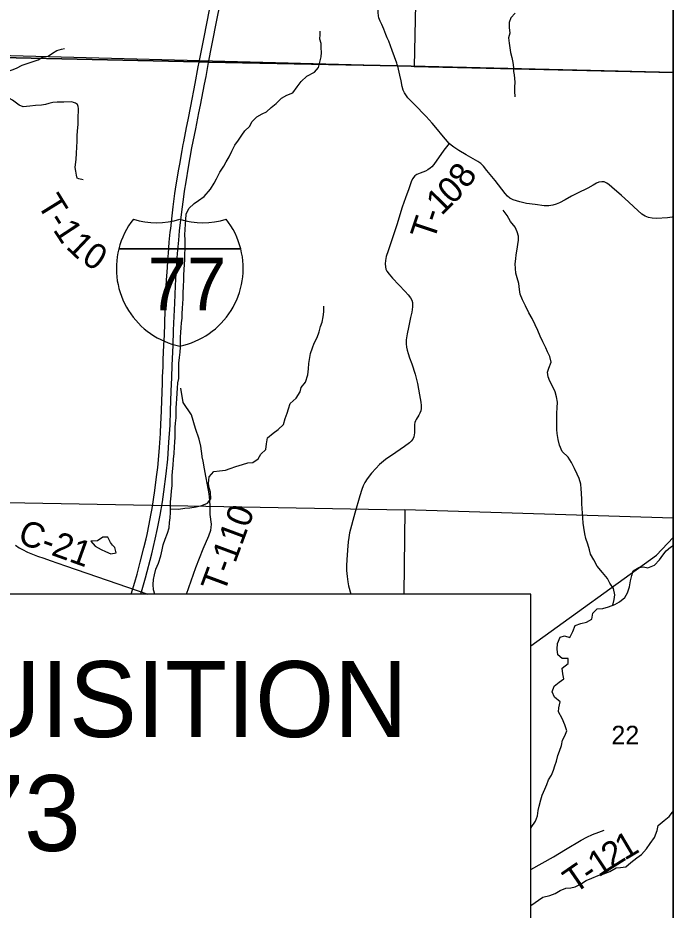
# Model space of a CAD drawing. Extents: x 0 to 34, y 0 to 22.
# Drawn here: x 6.964 to 8.431, y 18.153 to 20.15 of the extents above; entities that cross this region are included whole.
import ezdxf

# ---------------------------------------------------------------- set-up
doc = ezdxf.new("R2010")
doc.units = 0
for name, color, linetype in [('GM_X_Corporation', 7, 'Continuous'), ('GM_X_County_Road', 7, 'Continuous'), ('GM_X_County_Road_Text', 7, 'Continuous'), ('GM_X_Interstate_Location', 7, 'Continuous'), ('GM_X_Interstate_Route', 7, 'Continuous'), ('GM_X_Interstate_Shield', 7, 'Continuous'), ('GM_X_Minor_Lake', 7, 'Continuous'), ('GM_X_Minor_River', 7, 'Continuous'), ('GM_X_Section_Text', 7, 'Continuous'), ('GM_X_Township_Road', 7, 'Continuous'), ('GM_X_Township_Road_Text', 7, 'Continuous'), ('SH_Data', 7, 'Continuous'), ('SH_Text', 7, 'Continuous')]:
    doc.layers.add(name, color=color, linetype=linetype)

msp = doc.modelspace()

# ---------------------------------------------------------------- linework, layer by layer
at = {"layer": 'GM_X_Corporation'}
for points in [[(4.7823, 18.128), (4.7905, 18.3604), (4.8074, 19.5455), (4.8169, 20.042), (4.8194, 20.1261), (5.11, 20.116), (6.0551, 20.0845), (6.4901, 20.0752), (6.7204, 20.0659), (7.3691, 20.0515), (7.3901, 20.051), (7.814, 20.0425), (8.4311, 20.028), (8.4311, 21.3734), (1.6311, 21.3734)], [(4.0508, 18.1454), (4.7823, 18.128), (4.7905, 18.3604), (4.8074, 19.5455), (4.8169, 20.042), (4.8194, 20.1261), (5.11, 20.116), (6.0551, 20.0845), (6.4901, 20.0752), (6.7204, 20.0659), (7.3691, 20.0515), (7.3901, 20.051), (7.814, 20.0425), (8.4311, 20.028), (8.4311, 21.3734), (2.7987, 21.3734)], [(8.4311, 14.5734), (8.4311, 20.028), (7.814, 20.0425), (7.3901, 20.051), (7.3691, 20.0515), (6.7204, 20.0659), (6.4901, 20.0752), (6.0551, 20.0845), (5.11, 20.116), (4.8194, 20.1261), (4.8169, 20.042), (4.8074, 19.5455), (4.7905, 18.3604), (4.7823, 18.128)], [(8.4311, 16.0029), (8.4311, 20.028), (7.814, 20.0425), (7.3901, 20.051), (7.3691, 20.0515), (6.7204, 20.0659), (6.4901, 20.0752), (6.0551, 20.0845), (5.11, 20.116), (4.8194, 20.1261), (4.8169, 20.042), (4.8074, 19.5455), (4.7905, 18.3604), (4.7823, 18.128)], [(6.8097, 18.8602), (6.8161, 19.0676), (7.8304, 19.049), (7.8278, 18.8602)], [(7.8172, 18.0831), (7.817, 18.0695), (8.4311, 18.0575), (8.4311, 19.0302), (7.8304, 19.049), (7.8278, 18.8602)]]:
    msp.add_lwpolyline(points, dxfattribs=at)
for points in [[(7.8729, 21.0548), (7.8512, 20.0413), (6.8338, 20.0683), (6.8544, 21.0806)], [(8.4311, 20.0277), (8.4311, 21.0375), (7.8729, 21.0548), (7.8512, 20.0413)]]:
    msp.add_lwpolyline(points, close=True, dxfattribs=at)
at = {"layer": 'GM_X_County_Road'}
for points in [[(7.8142, 20.0419), (7.813, 20.0458), (7.812, 20.0487), (7.8069, 20.0627), (7.8021, 20.0771), (7.794, 20.0979), (7.791, 20.1052), (7.788, 20.1128), (7.7828, 20.1248), (7.7787, 20.1349), (7.7753, 20.143), (7.7722, 20.1503), (7.7711, 20.1543), (7.7706, 20.1623), (7.7703, 20.1705), (7.7703, 20.1795), (7.7703, 20.1879), (7.7706, 20.202), (7.7705, 20.2179), (7.7708, 20.2248), (7.7715, 20.2378), (7.7723, 20.2489), (7.7729, 20.2552)], [(8.4311, 19.7043), (8.429, 19.7038), (8.4182, 19.7022), (8.3939, 19.7011), (8.3844, 19.7018), (8.3758, 19.703), (8.3682, 19.7063), (8.3607, 19.7108), (8.3432, 19.7272), (8.3314, 19.738), (8.3151, 19.7521), (8.2938, 19.771), (8.2875, 19.7766), (8.2827, 19.7803), (8.2765, 19.7827), (8.2711, 19.7833), (8.2644, 19.7823), (8.2593, 19.7801), (8.2522, 19.7753), (8.2403, 19.7685), (8.2172, 19.7573), (8.2034, 19.7506), (8.1896, 19.743), (8.1769, 19.7363), (8.1688, 19.7331), (8.1616, 19.7308), (8.1527, 19.7293), (8.142, 19.7294), (8.1218, 19.7321), (8.1029, 19.7348), (8.0874, 19.7379), (8.0728, 19.7426), (8.0653, 19.7466), (8.0601, 19.7511), (8.0546, 19.7572), (8.0322, 19.7861), (8.0138, 19.8086), (8.0063, 19.818), (8.0001, 19.8242), (7.9936, 19.8285), (7.9674, 19.8434), (7.9515, 19.8529), (7.9398, 19.8606), (7.9338, 19.8653), (7.9292, 19.8691), (7.9214, 19.8787), (7.9129, 19.8884), (7.9035, 19.9001), (7.8915, 19.914), (7.878, 19.9295), (7.8509, 19.9571), (7.8429, 19.9648), (7.8371, 19.9711), (7.8336, 19.9752), (7.8291, 19.9821), (7.8264, 19.9881), (7.8239, 19.9965), (7.8218, 20.0089), (7.8193, 20.0215), (7.8142, 20.0419)], [(6.9585, 18.9695), (6.9663, 18.9641), (6.9739, 18.9598), (6.9855, 18.9538), (7.0078, 18.9452), (7.022, 18.9403), (7.0359, 18.9356), (7.0703, 18.9238), (7.1178, 18.9074), (7.2549, 18.8602)]]:
    msp.add_lwpolyline(points, dxfattribs=at)
at = {"layer": 'GM_X_Interstate_Route'}
for points in [[(7.3904, 20.0505), (7.3978, 20.088), (7.4101, 20.1489), (7.421, 20.2038)], [(7.3693, 20.0509), (7.3805, 20.1066), (7.3927, 20.1682)], [(7.2174, 18.8602), (7.2204, 18.8698), (7.2254, 18.8869), (7.2306, 18.9048), (7.2378, 18.9314), (7.2458, 18.9635), (7.2506, 18.9841), (7.2528, 18.9937), (7.2575, 19.0166), (7.2613, 19.0368), (7.2641, 19.052), (7.2704, 19.0924), (7.2741, 19.1225), (7.2767, 19.1437), (7.2775, 19.1519), (7.2808, 19.1882), (7.2829, 19.2195), (7.2838, 19.243), (7.2842, 19.2528), (7.2857, 19.2923), (7.2872, 19.3326), (7.2878, 19.3468), (7.2888, 19.3689), (7.2892, 19.3857), (7.2906, 19.4172), (7.2916, 19.4401), (7.2926, 19.4658), (7.2937, 19.4963), (7.2947, 19.5175), (7.2952, 19.534), (7.2967, 19.5638), (7.2976, 19.5807), (7.2991, 19.6041), (7.2996, 19.6103), (7.3006, 19.6223), (7.3027, 19.6478), (7.305, 19.6702), (7.3058, 19.6786), (7.3091, 19.7066), (7.3116, 19.7269), (7.3154, 19.7566), (7.3183, 19.776), (7.324, 19.8111), (7.326, 19.8225), (7.3315, 19.8535), (7.3341, 19.8666), (7.3352, 19.8723), (7.3415, 19.9043), (7.3449, 19.9221), (7.351, 19.9526), (7.361, 20.0033), (7.3674, 20.0401), (7.3693, 20.0509)], [(7.2386, 18.8602), (7.2497, 18.8969), (7.2639, 18.9507), (7.2713, 18.983), (7.2763, 19.0067), (7.282, 19.037), (7.2872, 19.0666), (7.2906, 19.0894), (7.2956, 19.1297), (7.2992, 19.162), (7.302, 19.2006), (7.3043, 19.2385), (7.3054, 19.2715), (7.3062, 19.2929), (7.3069, 19.3146), (7.3082, 19.3448), (7.3092, 19.3726), (7.311, 19.4164), (7.3124, 19.4503), (7.3131, 19.4668), (7.3148, 19.5117), (7.3165, 19.55), (7.3172, 19.565), (7.3195, 19.6015), (7.3211, 19.6223), (7.3237, 19.6527), (7.3259, 19.6732), (7.3313, 19.722), (7.3342, 19.7433), (7.3371, 19.7618), (7.3402, 19.7828), (7.3455, 19.8158), (7.3533, 19.8591), (7.3562, 19.8732), (7.362, 19.9018), (7.3689, 19.9375), (7.3723, 19.9544), (7.3815, 20.0013), (7.3851, 20.019), (7.3904, 20.0505)]]:
    msp.add_lwpolyline(points, dxfattribs=at)
at = {"layer": 'GM_X_Interstate_Shield'}
for p, q in [((7.1895, 19.6328), (7.4628, 19.6328)), ((7.4628, 19.6328), (7.1895, 19.6328)), ((7.4628, 19.6328), (7.1895, 19.6328))]:
    msp.add_line(p, q, dxfattribs=at)
for centre, start, end in [((7.3617, 19.5893), 141.669, 165.8066), ((7.2743, 19.8692), 253.0091, 286.9909), ((7.378, 19.8692), 253.0091, 286.9909), ((7.2906, 19.5893), 14.1934, 38.331), ((7.3617, 19.5893), 165.8066, 258.463), ((7.2906, 19.5893), 281.537, 14.1934)]:
    msp.add_arc(centre, 0.1776, start, end, dxfattribs=at)
at = {"layer": 'GM_X_Minor_Lake'}
for points in [[(7.1758, 18.9701), (7.1711, 18.9756), (7.1654, 18.9877), (7.1541, 18.9874), (7.1416, 18.9794), (7.1269, 18.9787)], [(7.1269, 18.9787), (7.1367, 18.9673), (7.1499, 18.9601), (7.1601, 18.9552), (7.1718, 18.9502), (7.1839, 18.9525), (7.1809, 18.9642), (7.1758, 18.9701)]]:
    msp.add_lwpolyline(points, dxfattribs=at)
at = {"layer": 'GM_X_Minor_River'}
for points in [[(8.0772, 20.1607), (8.0679, 20.15), (8.0638, 20.1397), (8.0635, 20.1287), (8.0655, 20.1159), (8.0626, 20.1052), (8.0638, 20.0931), (8.0654, 20.0833), (8.067, 20.0723), (8.0698, 20.061), (8.0721, 20.05), (8.0737, 20.039), (8.0738, 20.0296), (8.0742, 20.0281)], [(7.6371, 20.0393), (7.64, 20.0512), (7.643, 20.0626), (7.6432, 20.0728), (7.6428, 20.083), (7.6427, 20.0929), (7.6396, 20.1027), (7.6406, 20.1126), (7.6409, 20.1205)], [(7.009, 20.0558), (7.0196, 20.0629), (7.0313, 20.0641), (7.0411, 20.0707), (7.0512, 20.0768), (7.061, 20.0803), (7.0682, 20.0812)], [(6.7478, 20.0636), (6.7572, 20.0549), (6.7689, 20.0466), (6.7806, 20.0401), (6.7935, 20.0344), (6.8074, 20.0314), (6.8176, 20.0287), (6.8305, 20.0245), (6.843, 20.0196), (6.8528, 20.0165), (6.8668, 20.0138), (6.877, 20.0142), (6.8902, 20.0153), (6.9023, 20.0157), (6.9148, 20.0191), (6.9284, 20.0255), (6.9402, 20.0297), (6.9508, 20.0334), (6.9606, 20.0376), (6.9731, 20.044), (6.9891, 20.0495), (7.009, 20.0558)], [(7.3352, 19.5636), (7.3352, 19.5731), (7.336, 19.5875), (7.3368, 19.5974), (7.3376, 19.6095), (7.3372, 19.6205), (7.338, 19.6338), (7.3384, 19.6436), (7.3384, 19.6535), (7.3377, 19.6641), (7.3381, 19.6766), (7.3392, 19.688), (7.34, 19.6978), (7.3408, 19.7107), (7.3465, 19.7232), (7.3586, 19.7346), (7.3684, 19.741), (7.3809, 19.7501), (7.395, 19.7663), (7.4029, 19.78), (7.4086, 19.7895), (7.4158, 19.8046), (7.4246, 19.8179), (7.4302, 19.8277), (7.4367, 19.8391), (7.4428, 19.8519), (7.4492, 19.8648), (7.4579, 19.8762), (7.4651, 19.8875), (7.4716, 19.8974), (7.4822, 19.9068), (7.4883, 19.9178), (7.4985, 19.9284), (7.5106, 19.9349), (7.5205, 19.9398), (7.5307, 19.9492), (7.5417, 19.9587), (7.5538, 19.9704), (7.5663, 19.9772), (7.5792, 19.9825), (7.589, 19.9954), (7.5977, 20.0079), (7.6106, 20.0196), (7.628, 20.0284), (7.6371, 20.0393)], [(8.0742, 20.0281), (8.0757, 20.0152), (8.0768, 20.0053), (8.0761, 19.9958), (8.0761, 19.9856), (8.0764, 19.9735)], [(8.296, 18.8354), (8.2989, 18.8478), (8.3004, 18.8584), (8.2978, 18.8725), (8.2895, 18.885), (8.2838, 18.8948), (8.2729, 18.9085), (8.2612, 18.9225), (8.2537, 18.9366), (8.2461, 18.9495), (8.2435, 18.959), (8.2397, 18.9718), (8.2356, 18.9847), (8.233, 18.995), (8.2311, 19.0094), (8.2296, 19.0189), (8.2289, 19.031), (8.2278, 19.0412), (8.2274, 19.0515), (8.2267, 19.0621), (8.2263, 19.0719), (8.226, 19.0863), (8.2252, 19.0958), (8.2245, 19.106), (8.2207, 19.1186), (8.2162, 19.1288), (8.2098, 19.1417), (8.2038, 19.1546), (8.1959, 19.1667), (8.1827, 19.1793), (8.1763, 19.1937), (8.1736, 19.2066), (8.1714, 19.2194), (8.1707, 19.2289), (8.1707, 19.2653), (8.1711, 19.2774), (8.1723, 19.2896), (8.1697, 19.3017), (8.1667, 19.3131), (8.1618, 19.3241), (8.1546, 19.3366), (8.1512, 19.3465), (8.1497, 19.3567), (8.1528, 19.3662), (8.1577, 19.379), (8.1547, 19.3919), (8.1498, 19.4022), (8.1457, 19.4117), (8.1396, 19.4246), (8.1336, 19.4378), (8.1283, 19.4503), (8.1223, 19.4629), (8.1155, 19.4773), (8.108, 19.4898), (8.1005, 19.5057), (8.0937, 19.5186), (8.0888, 19.5315), (8.0873, 19.5417), (8.0854, 19.5554), (8.0821, 19.5683), (8.0791, 19.5785), (8.0779, 19.5891), (8.0776, 19.5998), (8.0787, 19.6104), (8.0799, 19.6198), (8.0814, 19.632), (8.0833, 19.6426), (8.0845, 19.6521), (8.0845, 19.6615), (8.0819, 19.671), (8.0774, 19.6812), (8.0672, 19.6945), (8.0593, 19.7074), (8.0506, 19.7199)], [(7.2705, 18.8601), (7.2673, 18.8697), (7.2666, 18.8815), (7.267, 18.8932), (7.2696, 18.9035), (7.2723, 18.916), (7.2788, 18.9296), (7.2841, 18.9459), (7.2871, 18.9592), (7.2891, 18.9705), (7.2936, 18.9834), (7.2986, 18.9967), (7.3024, 19.0088), (7.3035, 19.0205), (7.3047, 19.0311), (7.3051, 19.0425), (7.3051, 19.0543), (7.3055, 19.0668), (7.3067, 19.08), (7.3078, 19.091), (7.3094, 19.1024), (7.3094, 19.1123), (7.309, 19.1251), (7.3098, 19.135), (7.3113, 19.149), (7.3121, 19.1619), (7.3133, 19.1748), (7.3144, 19.1899), (7.3152, 19.2006), (7.3156, 19.2112), (7.3157, 19.2328), (7.3164, 19.2426), (7.318, 19.2551), (7.318, 19.2646), (7.3184, 19.2775), (7.3192, 19.287), (7.3196, 19.2976), (7.3203, 19.3097), (7.3211, 19.3215), (7.3219, 19.3328), (7.3238, 19.3427), (7.3242, 19.3522), (7.3243, 19.3772), (7.3254, 19.3897), (7.3269, 19.4014), (7.3281, 19.4128), (7.3281, 19.4352), (7.3285, 19.4454), (7.3293, 19.4568), (7.3301, 19.4674), (7.3313, 19.4776), (7.3317, 19.4878), (7.3321, 19.5004), (7.3332, 19.511), (7.3336, 19.5208), (7.3336, 19.5345), (7.3344, 19.5489), (7.3352, 19.5636)], [(7.3051, 19.0509), (7.3236, 19.0504), (7.3376, 19.0527), (7.3486, 19.0531), (7.363, 19.0557), (7.3758, 19.0587), (7.3883, 19.0636), (7.3959, 19.0735), (7.3948, 19.0883), (7.3922, 19.0981), (7.3903, 19.1076), (7.3918, 19.1224), (7.4021, 19.1345), (7.4149, 19.136), (7.4285, 19.1375), (7.4388, 19.1413), (7.452, 19.1458), (7.4664, 19.1503), (7.4789, 19.1537), (7.4895, 19.1548), (7.5016, 19.1632), (7.5076, 19.1734), (7.5186, 19.184), (7.5202, 19.1965), (7.5228, 19.2097), (7.535, 19.2203), (7.5467, 19.2283), (7.5588, 19.24), (7.5623, 19.2529), (7.5668, 19.265), (7.5695, 19.2749), (7.5737, 19.2866), (7.5865, 19.2991), (7.5956, 19.3131), (7.5983, 19.3226), (7.6074, 19.3347), (7.6127, 19.351), (7.6143, 19.3643), (7.6154, 19.3764), (7.6193, 19.3984), (7.6234, 19.4116), (7.6269, 19.4219), (7.6337, 19.4347), (7.6386, 19.4469), (7.6413, 19.459), (7.6447, 19.4692), (7.6474, 19.4806), (7.6489, 19.4919), (7.6486, 19.5048)], [(8.174, 18.5966), (8.1751, 18.6058), (8.1782, 18.6187), (8.1657, 18.6293), (8.1605, 18.6418), (8.1643, 18.6543), (8.176, 18.6634), (8.1862, 18.6706), (8.184, 18.682), (8.1829, 18.6945), (8.1957, 18.7047), (8.1961, 18.7164), (8.1829, 18.7161), (8.1731, 18.7244), (8.1712, 18.7366), (8.172, 18.7498), (8.1777, 18.7638), (8.1879, 18.7665), (8.2, 18.7631), (8.2065, 18.7763), (8.2114, 18.7899), (8.2247, 18.7945), (8.2368, 18.7975), (8.2489, 18.8039), (8.2512, 18.8179), (8.2606, 18.8274), (8.2735, 18.8281), (8.2864, 18.8315), (8.3004, 18.8372), (8.311, 18.8429), (8.3227, 18.8527), (8.3292, 18.8633), (8.3337, 18.8762), (8.3356, 18.8898), (8.3383, 18.9016), (8.3413, 18.9122), (8.3542, 18.9198), (8.3644, 18.9216), (8.3743, 18.9193), (8.3894, 18.925), (8.4004, 18.9367), (8.4083, 18.9474), (8.4152, 18.9572), (8.4254, 18.9651), (8.4311, 18.9687)], [(8.1124, 18.3357), (8.1132, 18.3374), (8.1227, 18.3519), (8.1272, 18.364), (8.129, 18.3758), (8.1313, 18.3856), (8.135, 18.3997), (8.138, 18.4099), (8.144, 18.4232), (8.1485, 18.4338), (8.1523, 18.4441), (8.1583, 18.4547), (8.1632, 18.4661), (8.1658, 18.4756), (8.1696, 18.4862), (8.173, 18.4987), (8.1763, 18.509), (8.1809, 18.5215), (8.1835, 18.5336), (8.1884, 18.5431), (8.1932, 18.5545), (8.1887, 18.5674), (8.1826, 18.5814), (8.174, 18.5966)], [(8.1124, 18.163), (8.1394, 18.1817), (8.155, 18.1859), (8.1671, 18.1898), (8.1784, 18.1966), (8.1905, 18.2016), (8.2019, 18.2024), (8.2117, 18.2047), (8.2238, 18.2112), (8.2366, 18.2192), (8.2487, 18.2242), (8.2631, 18.2303), (8.2756, 18.2341), (8.2892, 18.2395), (8.3036, 18.2475), (8.3134, 18.2479), (8.3252, 18.2498), (8.3361, 18.2597), (8.3497, 18.27), (8.3599, 18.2776), (8.3716, 18.2902), (8.3799, 18.3019), (8.3893, 18.3156), (8.395, 18.3312), (8.3976, 18.3422), (8.4112, 18.3532), (8.4225, 18.3624), (8.4297, 18.3719), (8.4311, 18.3748)]]:
    msp.add_lwpolyline(points, dxfattribs=at)
at = {"layer": 'GM_X_Township_Road'}
for points in [[(7.036, 19.9594), (7.0331, 19.9587), (7.0254, 19.9562), (7.0168, 19.9548), (7.0029, 19.9538), (6.9904, 19.9522), (6.9828, 19.9513), (6.9755, 19.9508), (6.9666, 19.955), (6.9513, 19.966), (6.9278, 19.9793), (6.8904, 20.0021), (6.8838, 20.0048), (6.878, 20.0065), (6.8688, 20.0088), (6.8519, 20.0137), (6.833, 20.0196), (6.7844, 20.0364), (6.751, 20.0483), (6.7337, 20.0533), (6.7297, 20.0554), (6.7259, 20.0587), (6.7206, 20.0654)], [(7.11, 19.7874), (7.0999, 19.7899), (7.0966, 19.7915), (7.0948, 19.7979), (7.0933, 19.8069), (7.0918, 19.8154), (7.0936, 19.8276), (7.0945, 19.8331), (7.0949, 19.8474), (7.0967, 19.8739), (7.0967, 19.886), (7.0973, 19.8973), (7.0988, 19.9116), (7.0988, 19.9187), (7.0986, 19.9273), (7.0993, 19.9436), (7.0993, 19.9474), (7.0984, 19.9513), (7.0971, 19.9558), (7.0924, 19.9591), (7.0884, 19.9609), (7.0846, 19.9619), (7.0663, 19.9617), (7.0513, 19.9615), (7.0419, 19.9607), (7.036, 19.9594)], [(7.9292, 19.8691), (7.9178, 19.8537), (7.8955, 19.8218), (7.8905, 19.8164), (7.8869, 19.8135), (7.8818, 19.8099), (7.8766, 19.8072), (7.8648, 19.8027), (7.8572, 19.7992), (7.8524, 19.7962), (7.8476, 19.7901), (7.8441, 19.7827), (7.839, 19.7676), (7.8317, 19.7474), (7.8244, 19.7265), (7.8192, 19.7089), (7.8128, 19.6887), (7.803, 19.6601), (7.7972, 19.6423), (7.7929, 19.6288), (7.7886, 19.6159), (7.7868, 19.6071), (7.7863, 19.5998), (7.7869, 19.5929), (7.788, 19.5877), (7.7901, 19.5831), (7.7952, 19.576), (7.8023, 19.5676), (7.8313, 19.5376), (7.8377, 19.5301), (7.8428, 19.5232), (7.8455, 19.5182), (7.8472, 19.5128), (7.8477, 19.503), (7.8456, 19.4916), (7.8427, 19.4791), (7.8384, 19.4567), (7.8354, 19.4428), (7.8334, 19.4292), (7.833, 19.4204), (7.8336, 19.4131), (7.8351, 19.406), (7.8375, 19.3989), (7.8409, 19.3887), (7.8459, 19.3755), (7.8532, 19.3527), (7.8584, 19.3315), (7.8631, 19.306), (7.8664, 19.2895), (7.8669, 19.2827), (7.867, 19.2755), (7.866, 19.2706), (7.8638, 19.2654), (7.8612, 19.2605), (7.8558, 19.2511), (7.8541, 19.2478), (7.8526, 19.2445), (7.8518, 19.2396), (7.8517, 19.2344), (7.8516, 19.2212), (7.8501, 19.2126), (7.8478, 19.2072), (7.8446, 19.2028), (7.8406, 19.1991), (7.8296, 19.1908), (7.8104, 19.1773), (7.7866, 19.1614), (7.7737, 19.1502), (7.765, 19.1416), (7.7558, 19.1309), (7.746, 19.1184), (7.7407, 19.1102), (7.737, 19.1029), (7.7336, 19.0942), (7.7296, 19.0805), (7.7184, 19.0414), (7.7064, 18.9975), (7.7046, 18.9868), (7.7033, 18.9772), (7.7016, 18.9587), (7.7, 18.9368), (7.6995, 18.9242), (7.6996, 18.9127), (7.7012, 18.8995), (7.7027, 18.8877), (7.7044, 18.879), (7.7091, 18.8602)], [(7.3762, 19.1688), (7.3732, 19.1914), (7.3693, 19.2071), (7.3616, 19.2307), (7.3521, 19.2615), (7.3335, 19.289), (7.3289, 19.3209)], [(7.3409, 18.8602), (7.3623, 18.9195), (7.3702, 18.9404), (7.3785, 18.9613), (7.3911, 18.991), (7.3954, 19.003), (7.3967, 19.0095), (7.3969, 19.0166), (7.3946, 19.0382), (7.3944, 19.057), (7.3936, 19.0699), (7.3918, 19.0847), (7.3884, 19.1045), (7.3842, 19.1243), (7.3814, 19.1403), (7.3784, 19.158), (7.3764, 19.1677), (7.3762, 19.1688)], [(8.1124, 18.7446), (8.3935, 18.9477), (8.4311, 18.9872)], [(8.1124, 18.244), (8.1628, 18.2724), (8.1898, 18.2887), (8.2252, 18.3094), (8.238, 18.3161), (8.2504, 18.322), (8.2644, 18.3276), (8.2763, 18.3315)]]:
    msp.add_lwpolyline(points, dxfattribs=at)
at = {"layer": 'SH_Data'}
msp.add_lwpolyline([(5.6652, 18.0831), (8.1124, 18.0831), (8.1124, 18.8602), (5.6652, 18.8602)], close=True, dxfattribs=at)
at = {"layer": 'SH_Text'}
msp.add_line((8.4311, 21.373), (8.4311, 14.5734), dxfattribs=at)

# ---------------------------------------------------------------- texts
at = {"layer": 'GM_X_County_Road_Text'}
msp.add_text('C-21', height=0.05682, rotation=340.163, dxfattribs=at).set_placement((6.9606, 18.9757))
at = {"layer": 'GM_X_Interstate_Location'}
for s in ['-', '.', ',']:
    msp.add_text(s, height=0.000189, dxfattribs=at).set_placement((7.3261, 19.5573))
msp.add_text('77', height=0.000189, rotation=0, dxfattribs=at).set_placement((7.2874, 19.5181))
at = {"layer": 'GM_X_Interstate_Shield'}
msp.add_text('77', height=0.11837, dxfattribs=at).set_placement((7.2542, 19.4952))
at = {"layer": 'GM_X_Section_Text'}
msp.add_text('22', height=0.04186, rotation=0, dxfattribs=at).set_placement((8.2928, 18.5236))
at = {"layer": 'GM_X_Township_Road_Text'}
for s, height, rotation, p in [('8', 0.0568, 56.8456, (7.9708, 19.7655)), ('0', 0.0568, 43.9181, (7.9367, 19.7305)), ('T', 0.0568, 301.776, (7.0053, 19.7332)), ('1', 0.0568, 45.5593, (7.9125, 19.7058)), ('-', 0.0568, 71.533, (7.9086, 19.6894)), ('1', 0.0568, 303.2897, (7.0409, 19.6759)), ('-', 0.0568, 301.9546, (7.0278, 19.6969)), ('T', 0.0568, 71.5678, (7.8951, 19.6491)), ('1', 0.0568, 316.4609, (7.0693, 19.6358)), ('0', 0.0568, 327.1668, (7.1037, 19.6045)), ('T-110', 0.05682, 69.6723, (7.4254, 18.8603)), ('1', 0.0568, 30.6692, (8.3223, 18.263)), ('2', 0.0568, 32.1571, (8.293, 18.2446)), ('1', 0.0568, 33.5501, (8.2641, 18.2254)), ('T', 0.0568, 34.597, (8.2101, 18.1883)), ('-', 0.0568, 34.3461, (8.245, 18.2124))]:
    msp.add_text(s, height=height, rotation=rotation, dxfattribs=at).set_placement(p)
at = {"layer": 'SH_Text'}
for s, p in [('END ACQUISITION', (5.8152, 18.5402)), ('S.L.M. 18.73', (5.8152, 18.2852))]:
    msp.add_text(s, height=0.17, dxfattribs=at).set_placement(p)

doc.saveas('drawing.dxf')
